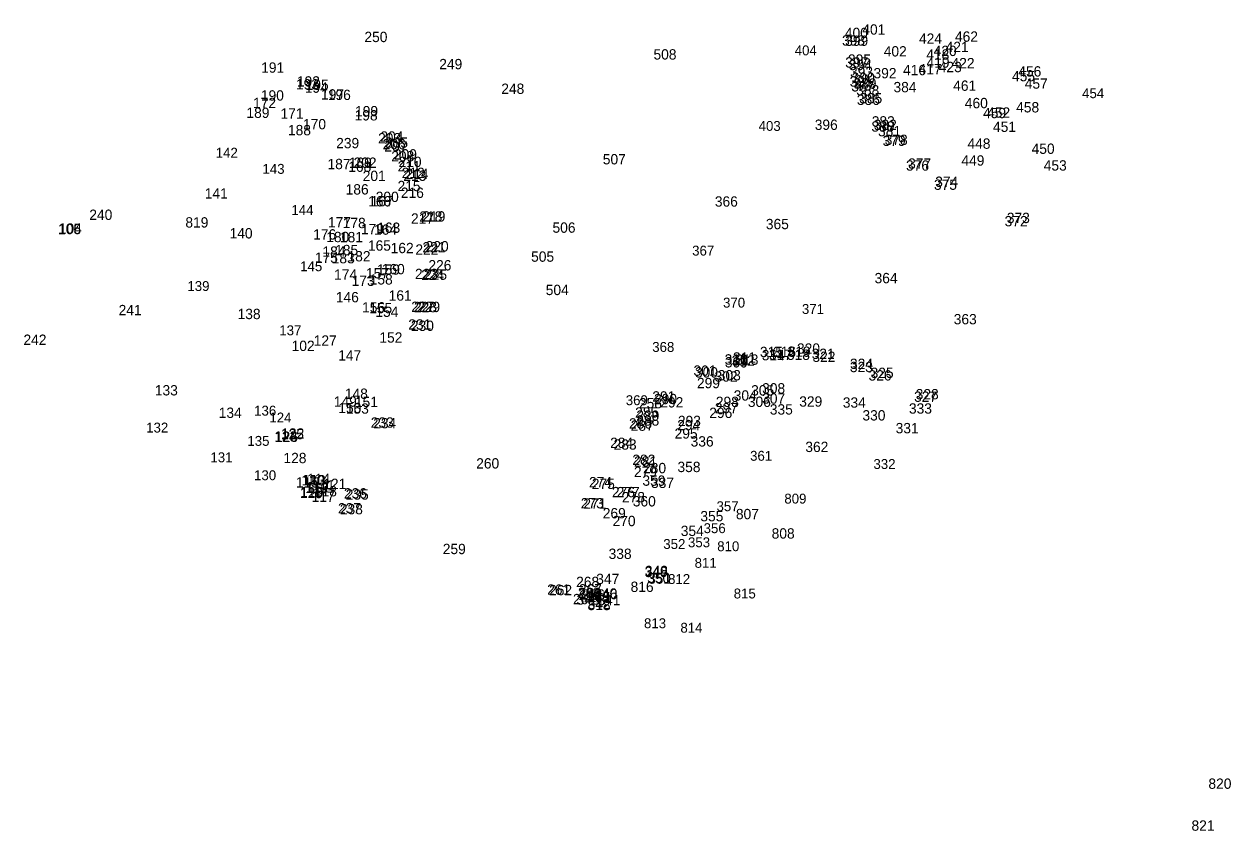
# Model space of a CAD drawing. Extents: x 359002 to 361405, y 1522603 to 1525369.
# Drawn here: x 359876.6 to 360169.3, y 1524358.7 to 1524554.2 of the extents above; entities that cross this region are included whole.
import ezdxf

# ---------------------------------------------------------------- set-up
doc = ezdxf.new("R2010")
doc.units = 0
for name, color, linetype in [('BWW_I', 7, 'Continuous'), ('DS_I', 7, 'Continuous'), ('LAPB_I', 7, 'Continuous'), ('LELB_I', 7, 'Continuous'), ('LELS_I', 7, 'Continuous'), ('LPST_I', 7, 'Continuous'), ('LTD_I', 7, 'Continuous'), ('LUKL_I', 7, 'Continuous'), ('LUKP_I', 7, 'Continuous'), ('PCH_I', 7, 'Continuous'), ('PE_I', 7, 'Continuous'), ('PRC_I', 7, 'Continuous'), ('RC_I', 7, 'Continuous'), ('RCD_I', 7, 'Continuous'), ('RDP_I', 7, 'Continuous'), ('RGB_I', 7, 'Continuous'), ('RSW_I', 7, 'Continuous'), ('S_I', 7, 'Continuous'), ('SRM_I', 7, 'Continuous'), ('TCBP_I', 7, 'Continuous'), ('TCSP_I', 7, 'Continuous'), ('UEO_I', 7, 'Continuous'), ('UP_I', 7, 'Continuous'), ('UPGW_I', 7, 'Continuous'), ('UPL_I', 7, 'Continuous'), ('UTMH_I', 7, 'Continuous')]:
    doc.layers.add(name, color=color, linetype=linetype)

msp = doc.modelspace()

# ---------------------------------------------------------------- texts
at = {"layer": 'BWW_I'}
for s, p in [('126', (359937.47, 1524452.92)), ('125', (359938.9, 1524453.58)), ('115', (359942.54, 1524441.87)), ('120', (359943.9, 1524442.4)), ('119', (359944.8, 1524440.52)), ('116', (359943.58, 1524439.53)), ('117', (359946.36, 1524438.4)), ('118', (359946.91, 1524439.73)), ('349', (360027.13, 1524420.16)), ('350', (360027.75, 1524418.72)), ('344', (360011.07, 1524414.83)), ('345', (360013.23, 1524414.07)), ('346', (360014.95, 1524414.8)), ('343', (360010.61, 1524413.48)), ('342', (360013.33, 1524412.39)), ('341', (360015.68, 1524413.34))]:
    msp.add_text(s, height=2.501, dxfattribs=at).set_placement(p)
at = {"layer": 'DS_I'}
for s, p in [('226', (359974.68, 1524494.49)), ('320', (360064.08, 1524474.31)), ('258', (360025.75, 1524461.07))]:
    msp.add_text(s, height=2.501, dxfattribs=at).set_placement(p)
at = {"layer": 'LAPB_I'}
for s, p in [('462', (360102.39, 1524549.93)), ('456', (360117.75, 1524541.49)), ('461', (360101.95, 1524538.03)), ('457', (360119.31, 1524538.54)), ('460', (360104.78, 1524533.81)), ('459', (360109.21, 1524531.4)), ('458', (360117.23, 1524532.79))]:
    msp.add_text(s, height=2.501, dxfattribs=at).set_placement(p)
at = {"layer": 'LELB_I'}
for s, p in [('394', (360076.65, 1524543.04)), ('393', (360076.94, 1524541.33)), ('392', (360082.63, 1524541.06)), ('392', (360082.63, 1524541.06)), ('455', (360116.23, 1524540.35)), ('388', (360078.45, 1524536.91)), ('384', (360087.48, 1524537.68)), ('385', (360079.17, 1524534.97)), ('189', (359930.55, 1524531.46)), ('382', (360082.7, 1524528.53)), ('188', (359940.62, 1524527.26)), ('187', (359950.21, 1524519.04)), ('211', (359967.22, 1524518.49)), ('453', (360123.92, 1524518.7)), ('141', (359920.45, 1524511.93)), ('186', (359954.61, 1524512.9)), ('200', (359961.91, 1524511.08)), ('177', (359950.32, 1524504.92)), ('178', (359953.9, 1524504.75)), ('140', (359926.46, 1524502.25)), ('176', (359946.73, 1524501.98)), ('179', (359958.32, 1524503.28)), ('179', (359958.32, 1524503.28)), ('180', (359949.91, 1524501.35)), ('181', (359953.23, 1524501.32)), ('165', (359960.01, 1524499.28)), ('175', (359947.14, 1524496.33)), ('184', (359948.98, 1524497.82)), ('183', (359951.23, 1524496.21)), ('182', (359955.06, 1524496.68)), ('174', (359951.81, 1524492.25)), ('173', (359956.06, 1524490.75)), ('157', (359959.54, 1524492.56)), ('157', (359959.54, 1524492.56)), ('156', (359958.6, 1524484.3)), ('138', (359928.4, 1524482.69)), ('312', (360048.22, 1524471.4)), ('303', (360044.87, 1524467.84)), ('133', (359908.33, 1524464.19)), ('149', (359951.74, 1524461.46)), ('304', (360048.73, 1524462.94)), ('334', (360075.19, 1524461.23)), ('134', (359923.83, 1524458.75)), ('335', (360057.48, 1524459.56)), ('333', (360091.23, 1524459.79)), ('123', (359937.3, 1524452.98)), ('122', (359939, 1524453.73)), ('336', (360038.28, 1524451.81)), ('128', (359939.53, 1524447.78)), ('113', (359944.18, 1524442.37)), ('113', (359944.18, 1524442.37)), ('112', (359944.97, 1524440.7)), ('114', (359945.26, 1524442.7)), ('337', (360028.67, 1524441.76)), ('129', (359943.52, 1524439.3)), ('109', (359947.26, 1524439.66)), ('338', (360018.39, 1524424.57)), ('348', (360027.19, 1524420.4)), ('816', (360023.72, 1524416.57)), ('351', (360027.96, 1524418.55)), ('265', (360010.94, 1524415.11)), ('266', (360011.91, 1524414.68)), ('339', (360013.17, 1524414.23)), ('340', (360014.91, 1524414.94)), ('340', (360014.91, 1524414.94)), ('818', (360013.27, 1524412.15))]:
    msp.add_text(s, height=2.501, dxfattribs=at).set_placement(p)
at = {"layer": 'LELS_I'}
for s, p in [('404', (360063.52, 1524546.63)), ('454', (360133.23, 1524536.25)), ('403', (360054.77, 1524528.32)), ('142', (359923.11, 1524521.83)), ('143', (359934.44, 1524517.91)), ('144', (359941.46, 1524507.95)), ('367', (360038.65, 1524498.1)), ('145', (359943.58, 1524494.31)), ('139', (359916.23, 1524489.51)), ('370', (360046.14, 1524485.49)), ('371', (360065.27, 1524483.95)), ('137', (359938.52, 1524478.77)), ('368', (360028.97, 1524474.75)), ('369', (360022.55, 1524461.84)), ('136', (359932.42, 1524459.31)), ('124', (359936.12, 1524457.64)), ('132', (359906.23, 1524455.21)), ('135', (359930.78, 1524451.98)), ('131', (359921.82, 1524448)), ('361', (360052.7, 1524448.36)), ('332', (360082.62, 1524446.38)), ('130', (359932.4, 1524443.65)), ('809', (360061.01, 1524437.99)), ('357', (360044.56, 1524436.14)), ('356', (360041.43, 1524430.82)), ('352', (360031.65, 1524426.98)), ('353', (360037.64, 1524427.4)), ('810', (360044.73, 1524426.44)), ('811', (360039.25, 1524422.42)), ('812', (360032.81, 1524418.5)), ('815', (360048.73, 1524414.99)), ('813', (360026.97, 1524407.78)), ('814', (360035.8, 1524406.69))]:
    msp.add_text(s, height=2.4, dxfattribs=at).set_placement(p)
at = {"layer": 'LPST_I'}
for s, p in [('190', (359934.05, 1524535.66)), ('452', (360110.2, 1524531.51)), ('451', (360111.62, 1524528.07)), ('355', (360040.64, 1524433.68)), ('354', (360035.89, 1524430.12))]:
    msp.add_text(s, height=2.501, dxfattribs=at).set_placement(p)
at = {"layer": 'LTD_I'}
for s, p in [('450', (360120.98, 1524522.75)), ('127', (359946.87, 1524476.25)), ('362', (360066.1, 1524450.48)), ('358', (360035.09, 1524445.61))]:
    msp.add_text(s, height=2.501, dxfattribs=at).set_placement(p)
at = {"layer": 'LUKL_I'}
for s, p in [('452', (360110.2, 1524531.51)), ('451', (360111.62, 1524528.07)), ('240', (359892.44, 1524506.74)), ('241', (359899.55, 1524483.64)), ('242', (359876.47, 1524476.45)), ('107', (359946.55, 1524438.04)), ('108', (359947.07, 1524437.81)), ('237', (359952.75, 1524435.6)), ('238', (359953.21, 1524435.38)), ('259', (359978.17, 1524425.73)), ('261', (360003.48, 1524415.89)), ('262', (360003.95, 1524415.76)), ('263', (360010.22, 1524413.37))]:
    msp.add_text(s, height=2.501, dxfattribs=at).set_placement(p)
at = {"layer": 'LUKP_I'}
for s, p in [('105', (359884.87, 1524503.34)), ('106', (359884.87, 1524503.28)), ('104', (359885.05, 1524503.39)), ('102', (359941.51, 1524474.97)), ('820', (360163.86, 1524368.85)), ('821', (360159.76, 1524358.69))]:
    msp.add_text(s, height=2.501, dxfattribs=at).set_placement(p)
at = {"layer": 'PCH_I'}
for s, p in [('397', (360075.77, 1524543.67)), ('396', (360068.38, 1524528.56))]:
    msp.add_text(s, height=2.501, dxfattribs=at).set_placement(p)
at = {"layer": 'PE_I'}
for s, p in [('398', (360075, 1524548.98)), ('191', (359934.12, 1524542.42)), ('397', (360075.77, 1524543.67)), ('192', (359942.79, 1524539.06)), ('195', (359944.91, 1524538.25)), ('391', (360076.85, 1524539.05)), ('387', (360077.24, 1524537.87)), ('196', (359950.28, 1524535.8)), ('386', (360078.6, 1524534.61)), ('199', (359956.9, 1524531.85)), ('380', (360082.12, 1524528.13)), ('204', (359963.03, 1524525.71)), ('205', (359964.15, 1524524.24)), ('379', (360084.84, 1524524.68)), ('209', (359966.31, 1524521.38)), ('210', (359967.44, 1524519.56)), ('214', (359969.14, 1524516.66)), ('376', (360090.52, 1524518.68)), ('375', (360097.29, 1524514.03)), ('219', (359973.22, 1524506.34)), ('372', (360114.43, 1524505.18)), ('220', (359974.02, 1524499.1)), ('225', (359973.63, 1524492.23)), ('229', (359971.95, 1524484.4)), ('230', (359970.44, 1524479.83)), ('311', (360048.55, 1524472.15)), ('315', (360055.09, 1524473.48)), ('316', (360058.27, 1524473.51)), ('319', (360061.78, 1524473.56)), ('321', (360067.63, 1524473.04)), ('310', (360046.52, 1524471.68)), ('324', (360076.93, 1524470.61)), ('301', (360038.97, 1524468.96)), ('325', (360081.93, 1524468.42)), ('291', (360028.99, 1524462.71)), ('328', (360092.87, 1524463.25)), ('285', (360024.81, 1524458.81)), ('234', (359961.3, 1524456.22)), ('284', (360018.76, 1524451.46)), ('274', (360013.63, 1524441.92)), ('235', (359954.63, 1524438.93)), ('238', (359953.21, 1524435.38)), ('273', (360011.64, 1524436.83)), ('261', (360003.48, 1524415.89))]:
    msp.add_text(s, height=2.501, dxfattribs=at).set_placement(p)
at = {"layer": 'PRC_I'}
for s, p in [('250', (359959.16, 1524549.84)), ('508', (360029.27, 1524545.61)), ('249', (359977.31, 1524543.26)), ('248', (359992.36, 1524537.29)), ('507', (360016.98, 1524520.2)), ('366', (360044.15, 1524509.96)), ('365', (360056.52, 1524504.49)), ('364', (360082.89, 1524491.39)), ('504', (360003.14, 1524488.52)), ('363', (360102.09, 1524481.43)), ('260', (359986.27, 1524446.48)), ('259', (359978.17, 1524425.73))]:
    msp.add_text(s, height=2.501, dxfattribs=at).set_placement(p)
at = {"layer": 'RC_I'}
for s, p in [('400', (360075.69, 1524550.81)), ('393', (360076.94, 1524541.33)), ('390', (360077.36, 1524539.92)), ('193', (359942.56, 1524538.36)), ('192', (359942.79, 1524539.06)), ('194', (359944.71, 1524537.56)), ('389', (360077.78, 1524538.54)), ('388', (360078.45, 1524536.91)), ('197', (359948.64, 1524535.92)), ('198', (359956.79, 1524530.85)), ('203', (359962.47, 1524525.28)), ('381', (360083.73, 1524527.01)), ('378', (360085.35, 1524524.9)), ('377', (360091.03, 1524519.15)), ('213', (359968.6, 1524516.21)), ('374', (360097.6, 1524514.75)), ('218', (359972.48, 1524506.32)), ('373', (360114.97, 1524505.97)), ('221', (359973.23, 1524498.85)), ('224', (359972.92, 1524492.15)), ('228', (359971.17, 1524484.37)), ('231', (359969.8, 1524480.15)), ('317', (360057.29, 1524472.82)), ('318', (360061.63, 1524472.81)), ('322', (360067.82, 1524472.32)), ('309', (360046.58, 1524470.98)), ('323', (360076.9, 1524469.84)), ('300', (360039.33, 1524468.54)), ('326', (360081.43, 1524467.81)), ('290', (360029.4, 1524462.08)), ('327', (360092.47, 1524462.64)), ('289', (360025.1, 1524458.05)), ('233', (359960.7, 1524456.38)), ('286', (360023.33, 1524456.17)), ('283', (360019.6, 1524451.05)), ('275', (360014.31, 1524441.52)), ('236', (359954.19, 1524439.21)), ('237', (359952.75, 1524435.6)), ('271', (360012.26, 1524436.73)), ('262', (360003.95, 1524415.76))]:
    msp.add_text(s, height=2.501, dxfattribs=at).set_placement(p)
at = {"layer": 'RCD_I'}
for s, p in [('400', (360075.69, 1524550.81)), ('399', (360075.76, 1524548.92)), ('395', (360076.45, 1524544.36)), ('394', (360076.65, 1524543.04)), ('393', (360076.94, 1524541.33)), ('388', (360078.45, 1524536.91)), ('385', (360079.17, 1524534.97)), ('383', (360082.21, 1524529.37)), ('382', (360082.7, 1524528.53)), ('203', (359962.47, 1524525.28)), ('381', (360083.73, 1524527.01)), ('206', (359963.59, 1524523.87)), ('207', (359963.99, 1524523.31)), ('208', (359965.66, 1524520.91)), ('211', (359967.22, 1524518.49)), ('212', (359968.21, 1524516.9)), ('213', (359968.6, 1524516.21)), ('314', (360055.53, 1524472.71)), ('317', (360057.29, 1524472.82)), ('309', (360046.58, 1524470.98)), ('312', (360048.22, 1524471.4)), ('313', (360049.15, 1524471.63))]:
    msp.add_text(s, height=2.501, dxfattribs=at).set_placement(p)
at = {"layer": 'RDP_I'}
for s, p in [('202', (359956.52, 1524519.36)), ('168', (359955.24, 1524518.39)), ('166', (359960.07, 1524510.01)), ('164', (359961.49, 1524503.15)), ('159', (359962.19, 1524493.46)), ('158', (359960.45, 1524491.08)), ('155', (359960.32, 1524484.11)), ('308', (360055.62, 1524464.67)), ('306', (360052.16, 1524461.41)), ('307', (360055.63, 1524462.2)), ('150', (359952.83, 1524459.9)), ('296', (360042.8, 1524458.72)), ('295', (360034.39, 1524453.73)), ('279', (360024.53, 1524444.42)), ('111', (359946.4, 1524441.17)), ('110', (359947.57, 1524440.6)), ('278', (360021.63, 1524438.29)), ('270', (360019.35, 1524432.51)), ('266', (360011.91, 1524414.68))]:
    msp.add_text(s, height=2.501, dxfattribs=at).set_placement(p)
at = {"layer": 'RGB_I'}
for s, p in [('172', (359932.16, 1524533.84)), ('171', (359938.81, 1524531.28)), ('170', (359944.27, 1524528.7)), ('169', (359955.38, 1524519.35)), ('167', (359960.68, 1524510.03)), ('163', (359962.26, 1524503.6)), ('160', (359963.36, 1524493.56)), ('158', (359960.45, 1524491.08)), ('154', (359961.83, 1524483.23)), ('154', (359961.83, 1524483.23)), ('306', (360052.16, 1524461.41)), ('329', (360064.62, 1524461.48)), ('153', (359954.66, 1524459.78)), ('297', (360044.16, 1524459.86)), ('330', (360079.95, 1524458.12)), ('294', (360035.02, 1524455.76)), ('331', (360088.01, 1524455.02)), ('281', (360024.57, 1524446.93)), ('280', (360026.75, 1524445.34)), ('108', (359947.07, 1524437.81)), ('277', (360020.34, 1524439.51)), ('277', (360020.34, 1524439.51)), ('264', (360009.74, 1524413.59))]:
    msp.add_text(s, height=2.501, dxfattribs=at).set_placement(p)
at = {"layer": 'RSW_I'}
for s, p in [('400', (360075.69, 1524550.81)), ('424', (360093.66, 1524549.43)), ('402', (360085.11, 1524546.35)), ('418', (360095.44, 1524545.59)), ('420', (360097.22, 1524546.46)), ('421', (360100.13, 1524547.42)), ('423', (360098.46, 1524542.55)), ('422', (360101.56, 1524543.49)), ('416', (360089.8, 1524541.82)), ('417', (360093.56, 1524542.02)), ('384', (360087.48, 1524537.68)), ('203', (359962.47, 1524525.28)), ('381', (360083.73, 1524527.01)), ('202', (359956.52, 1524519.36)), ('201', (359958.75, 1524516.17)), ('212', (359968.21, 1524516.9)), ('215', (359967.19, 1524513.71)), ('200', (359961.91, 1524511.08)), ('216', (359968, 1524512.08)), ('217', (359970.46, 1524505.83)), ('162', (359965.53, 1524498.68)), ('222', (359971.53, 1524498.31)), ('223', (359971.42, 1524492.39)), ('161', (359965.05, 1524487.17)), ('227', (359970.52, 1524484.44)), ('227', (359970.52, 1524484.44)), ('228', (359971.17, 1524484.37)), ('152', (359962.79, 1524476.99)), ('317', (360057.29, 1524472.82)), ('309', (360046.58, 1524470.98)), ('302', (360044.09, 1524467.54)), ('303', (360044.87, 1524467.84)), ('299', (360039.82, 1524465.95)), ('305', (360052.96, 1524464.18)), ('308', (360055.62, 1524464.67)), ('151', (359956.85, 1524461.37)), ('292', (360030.93, 1524461.28)), ('298', (360044.4, 1524461.39)), ('304', (360048.73, 1524462.94)), ('286', (360023.33, 1524456.17)), ('287', (360023.75, 1524455.63)), ('288', (360025.09, 1524456.89)), ('293', (360035.19, 1524456.76)), ('282', (360024.15, 1524447.35)), ('110', (359947.57, 1524440.6)), ('121', (359949.18, 1524441.52)), ('107', (359946.55, 1524438.04)), ('109', (359947.26, 1524439.66)), ('276', (360019.19, 1524439.52)), ('269', (360016.97, 1524434.4)), ('268', (360010.51, 1524417.75)), ('265', (360010.94, 1524415.11)), ('267', (360011.17, 1524415.95)), ('263', (360010.22, 1524413.37))]:
    msp.add_text(s, height=2.501, dxfattribs=at).set_placement(p)
at = {"layer": 'S_I'}
for s, p in [('448', (360105.42, 1524523.98)), ('449', (360103.95, 1524519.9)), ('146', (359952.23, 1524486.77)), ('147', (359952.8, 1524472.65)), ('347', (360015.39, 1524418.47))]:
    msp.add_text(s, height=2.501, dxfattribs=at).set_placement(p)
at = {"layer": 'SRM_I'}
msp.add_text('347', height=2.501, dxfattribs=at).set_placement((360015.39, 1524418.47))
at = {"layer": 'TCBP_I'}
for s, p in [('401', (360079.92, 1524551.65)), ('239', (359952.31, 1524524.11)), ('148', (359954.42, 1524463.36)), ('359', (360026.59, 1524442.3)), ('360', (360024.25, 1524437.29))]:
    msp.add_text(s, height=2.501, dxfattribs=at).set_placement(p)
at = {"layer": 'TCSP_I'}
for s, p in [('419', (360095.49, 1524543.63)), ('185', (359952.06, 1524498.19))]:
    msp.add_text(s, height=2.501, dxfattribs=at).set_placement(p)
at = {"layer": 'UEO_I'}
for s, p in [('819', (359915.74, 1524504.89)), ('819', (359915.74, 1524504.89)), ('807', (360049.26, 1524434.19))]:
    msp.add_text(s, height=2.501, dxfattribs=at).set_placement(p)
at = {"layer": 'UP_I'}
msp.add_text('807', height=2.501, dxfattribs=at).set_placement((360049.26, 1524434.19))
at = {"layer": 'UPGW_I'}
msp.add_text('808', height=2.501, dxfattribs=at).set_placement((360057.93, 1524429.5))
at = {"layer": 'UPL_I'}
msp.add_text('819', height=2.501, dxfattribs=at).set_placement((359915.74, 1524504.89))
at = {"layer": 'UTMH_I'}
for s, p in [('506', (360004.78, 1524503.63)), ('505', (359999.59, 1524496.6))]:
    msp.add_text(s, height=2.501, dxfattribs=at).set_placement(p)

doc.saveas('drawing.dxf')
